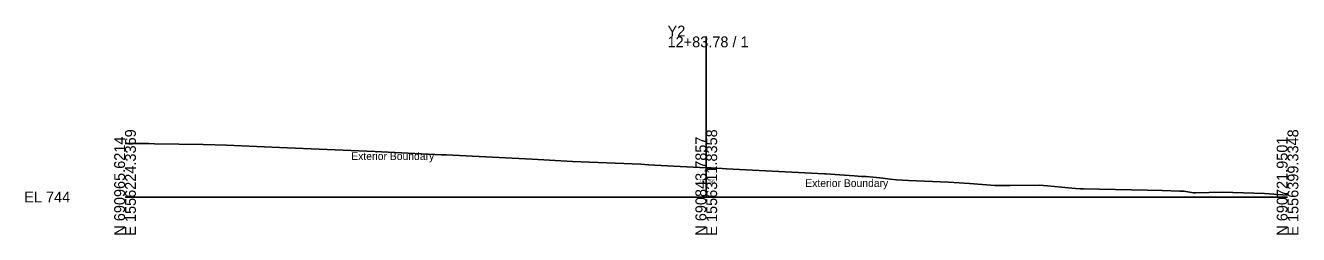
# Model space of a CAD drawing. Extents: x -26 to 303, y -10 to 5027.
# Drawn here: x -25.7 to 302.8, y 2990.3 to 3044.3 of the extents above; entities that cross this region are included whole.
import ezdxf

# ---------------------------------------------------------------- set-up
doc = ezdxf.new("R2010")
doc.units = 0
for name, color, linetype in [('Default', 7, 'Continuous'), ('Exist Cross Section Cell', 7, 'Continuous'), ('Exist XS Center Line Elevation Label', 7, 'Continuous'), ('Exist XS Ground Line', 7, 'Continuous')]:
    doc.layers.add(name, color=color, linetype=linetype)

msp = doc.modelspace()

# ---------------------------------------------------------------- linework, layer by layer
at = {"layer": 'Exist Cross Section Cell'}
for p, q in [((150, 3000), (150, 3041.45)), ((0, 3000), (150, 3000)), ((150, 3000), (300, 3000))]:
    msp.add_line(p, q, dxfattribs=at)
at = {"layer": 'Exist XS Ground Line'}
msp.add_lwpolyline([(0, 3013.78), (1.77, 3013.82), (3.51, 3013.83), (6.06, 3013.79), (7.58, 3013.75), (20.2, 3013.57), (26.16, 3013.38), (36.02, 3012.98), (39.9, 3012.82), (64.5, 3011.72), (81.67, 3010.91), (82.54, 3010.87), (82.85, 3010.85), (105.11, 3009.77), (115.46, 3009.2), (133.09, 3008.44), (135.09, 3008.35), (141.63, 3007.98), (150, 3007.56), (151.18, 3007.5), (154.07, 3007.37), (155.22, 3007.3), (180.48, 3006.02), (180.92, 3005.98), (184.36, 3005.75), (188.14, 3005.5), (190.02, 3005.31), (191.26, 3005.26), (193.05, 3005.15), (195.53, 3004.87), (197.46, 3004.63), (199.12, 3004.41), (202.18, 3004.26), (212.55, 3003.86), (217.96, 3003.46), (224.47, 3002.96), (228.32, 3002.93), (235.98, 3003.05), (238.07, 3002.9), (245.25, 3002.24), (246.57, 3002.12), (247.31, 3002.1), (263.82, 3001.79), (267.68, 3001.72), (272.2, 3001.54), (273.32, 3001.47), (275.65, 3001.12), (276.29, 3001.08), (283.21, 3001.25), (291.28, 3001), (294.03, 3000.87), (300, 3000.51)], dxfattribs=at)

# ---------------------------------------------------------------- texts
at = {"layer": 'Default'}
for s, height, p in [('Exterior Boundary', 2, (58.38, 3009.55)), ('Exterior Boundary', 2, (175.55, 3002.59)), ('-', 0.0001, (0, 3000)), ('-', 0.0001, (0, 3000))]:
    msp.add_text(s, height=height, dxfattribs=at).set_placement(p)
at = {"layer": 'Exist Cross Section Cell'}
for s, p in [('Y2', (140, 3041.45)), ('12+83.78 / 1', (140, 3038.65)), ('EL 744', (-26, 2998.6))]:
    msp.add_text(s, height=2.8, dxfattribs=at).set_placement(p)
for s, p in [('E 1556224.3369', (2.8, 2990)), ('E 1556311.8358', (152.8, 2990)), ('E 1556399.3348', (302.8, 2990)), ('N 690965.6214', (0, 2990)), ('N 690843.7857', (150, 2990)), ('N 690721.9501', (300, 2990))]:
    msp.add_text(s, height=2.8, rotation=90, dxfattribs=at).set_placement(p)
at = {"layer": 'Exist XS Center Line Elevation Label'}
msp.add_text('751.56', height=1, dxfattribs=at).set_placement((148.01, 3003.56))

doc.saveas('drawing.dxf')
